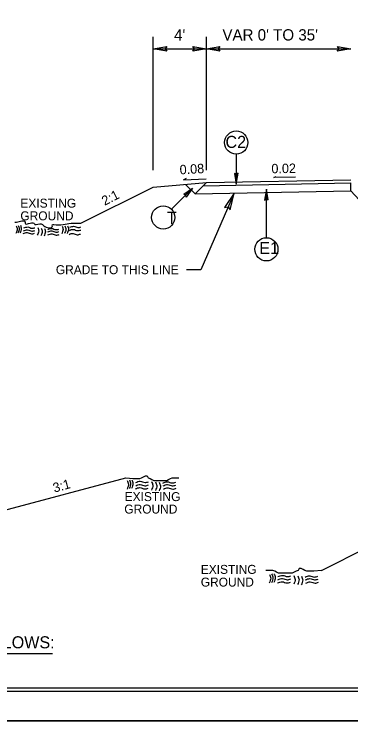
# Model space of a CAD drawing. Extents: x 573813 to 575363, y -54752 to -53123.
# Drawn here: x 574782.7 to 574833.5, y -54223.4 to -54116.8 of the extents above; entities that cross this region are included whole.
import ezdxf

# ---------------------------------------------------------------- set-up
doc = ezdxf.new("R2010")
doc.units = 0
for name, color, linetype in [('Old_Level_1', 7, 'Continuous'), ('Old_Level_11', 7, 'Continuous'), ('Old_Level_2', 7, 'Continuous'), ('Prop Dimension', 7, 'Continuous'), ('Prop Dimension Text', 7, 'Continuous'), ('Sheet Cutting Line CELL', 7, 'Continuous'), ('Sheet Plot Border Inside CELL', 7, 'Continuous'), ('Sheet Plot Border Outside CELL', 7, 'Continuous'), ('Sheet Typical CELL', 7, 'Continuous'), ('Typical ID Circle CELL', 7, 'Continuous'), ('Typical Pavement Slope CELL', 7, 'Continuous'), ('Typical Pavement Slope Information CELL', 7, 'Continuous'), ('Typical Shoulder Slope Information CELL', 7, 'Continuous'), ('Typical Terminator CELL', 7, 'Continuous'), ('Typical Text General CELL', 7, 'Continuous'), ('Typical Text ID Circle CELL', 7, 'Continuous')]:
    doc.layers.add(name, color=color, linetype=linetype)

msp = doc.modelspace()

# ---------------------------------------------------------------- linework, layer by layer
at = {"layer": 'Old_Level_1'}
for p, q in [((574821.89, -54141.45), (574822.27, -54141.27)), ((574825.16, -54141.39), (574821.89, -54141.45)), ((574803.69, -54142.87), (574811.7, -54142.21)), ((574808.26, -54141.8), (574808.71, -54141.51)), ((574808.26, -54141.8), (574811.69, -54141.63)), ((574808.56, -54142.47), (574810, -54143.91)), ((574811.7, -54142.21), (574810, -54143.91)), ((574811.24, -54142.67), (574833.53, -54142.23)), ((574811.7, -54142.21), (574833.53, -54141.77)), ((574792.76, -54148.34), (574803.69, -54142.87)), ((574810, -54143.91), (574833.53, -54143.44)), ((574781.07, -54191.67), (574799.55, -54186.73)), ((574829.1, -54200.71), (574852.24, -54189.13))]:
    msp.add_line(p, q, dxfattribs=at)
for points in [[(574799.55, -54186.73), (574800.67, -54186.87), (574800.95, -54186.87), (574801.37, -54186.87), (574801.65, -54186.87), (574801.93, -54186.73), (574802.21, -54186.59), (574802.49, -54186.45), (574802.77, -54186.45), (574802.91, -54186.73), (574803.19, -54186.87), (574803.47, -54187.01), (574803.75, -54187.15), (574804.03, -54187.15), (574804.31, -54187.15), (574804.59, -54187.15), (574804.87, -54187.15), (574805.15, -54187.15), (574805.43, -54187.15), (574805.71, -54187.15), (574805.99, -54187.01), (574806.27, -54186.87), (574806.55, -54186.73), (574806.97, -54186.73), (574807.25, -54186.73), (574807.53, -54186.73)], [(574829.1, -54200.71), (574827.92, -54200.85), (574827.62, -54200.85), (574827.18, -54200.85), (574826.89, -54200.85), (574826.59, -54200.71), (574826.3, -54200.56), (574826, -54200.41), (574825.71, -54200.41), (574825.56, -54200.71), (574825.26, -54200.85), (574824.97, -54201), (574824.67, -54201.15), (574824.38, -54201.15), (574824.08, -54201.15), (574823.79, -54201.15), (574823.49, -54201.15), (574823.2, -54201.15), (574822.9, -54201.15), (574822.61, -54201.15), (574822.31, -54201), (574822.02, -54200.85), (574821.72, -54200.71), (574821.28, -54200.71), (574820.99, -54200.71), (574820.69, -54200.71)]]:
    msp.add_lwpolyline(points, dxfattribs=at)
at = {"layer": 'Old_Level_11'}
msp.add_line((574736.55, -54213.27), (574788.44, -54213.27), dxfattribs=at)
for points in [[(574805.74, -54122.36), (574803.69, -54122), (574805.75, -54121.64), (574805.49, -54122)], [(574809.66, -54121.65), (574811.7, -54122), (574809.65, -54122.37), (574809.91, -54122)], [(574813.75, -54122.36), (574811.7, -54122), (574813.76, -54121.64), (574813.5, -54122)], [(574831.49, -54121.65), (574833.53, -54122), (574831.48, -54122.37), (574831.74, -54122)]]:
    msp.add_lwpolyline(points, close=True, dxfattribs=at)
at = {"layer": 'Old_Level_2'}
for points in [[(574782.78, -54148.17), (574783.01, -54148.15), (574784.32, -54148.15), (574784.32, -54148.34), (574785.63, -54148.34), (574785.82, -54148.52), (574786.01, -54148.52), (574786.95, -54148.52), (574787.13, -54148.71), (574788.45, -54148.71), (574788.45, -54148.52), (574788.64, -54148.52), (574791.26, -54148.34), (574792.76, -54148.34)], [(574783, -54148.7), (574783.14, -54149.21), (574782.93, -54149.86)], [(574783.29, -54148.66), (574783.44, -54149.16), (574783.23, -54149.81)], [(574783.61, -54148.64), (574783.75, -54149.14), (574783.54, -54149.79)], [(574784.12, -54149.05), (574784.73, -54148.9), (574785.36, -54149.09), (574785.82, -54149.01)], [(574789.91, -54148.76), (574790.06, -54149.27), (574789.85, -54149.92)], [(574790.33, -54148.74), (574790.48, -54149.25), (574790.27, -54149.9)], [(574790.73, -54148.7), (574790.88, -54149.21), (574790.67, -54149.86)], [(574791.06, -54148.94), (574791.66, -54148.8), (574792.3, -54148.98), (574792.76, -54148.9)], [(574784.04, -54149.89), (574784.65, -54149.74), (574785.28, -54149.93), (574785.74, -54149.85)], [(574784.1, -54149.47), (574784.71, -54149.32), (574785.34, -54149.51), (574785.8, -54149.43)], [(574786.23, -54149), (574786.38, -54149.5), (574786.17, -54150.15)], [(574786.76, -54149.06), (574786.91, -54149.56), (574786.7, -54150.21)], [(574787.24, -54149.12), (574787.39, -54149.63), (574787.18, -54150.28)], [(574787.74, -54149.26), (574788.34, -54149.11), (574788.98, -54149.3), (574789.44, -54149.22)], [(574787.74, -54149.64), (574788.34, -54149.49), (574788.98, -54149.68), (574789.44, -54149.59)], [(574787.78, -54150.08), (574788.39, -54149.93), (574789.02, -54150.12), (574789.48, -54150.04)], [(574790.97, -54150.01), (574791.58, -54149.87), (574792.21, -54150.06), (574792.67, -54149.97)], [(574791.03, -54149.41), (574791.64, -54149.26), (574792.27, -54149.45), (574792.74, -54149.36)], [(574799.74, -54187.13), (574799.93, -54187.7), (574799.73, -54188.45)], [(574799.74, -54187.13), (574799.93, -54187.7), (574799.73, -54188.45)], [(574800.07, -54187.07), (574800.26, -54187.63), (574800.06, -54188.38)], [(574800.07, -54187.07), (574800.26, -54187.63), (574800.06, -54188.38)], [(574800.43, -54187.03), (574800.62, -54187.6), (574800.41, -54188.34)], [(574800.43, -54187.03), (574800.62, -54187.6), (574800.41, -54188.34)], [(574801.03, -54187.47), (574801.71, -54187.27), (574802.44, -54187.46), (574802.96, -54187.34)], [(574800.98, -54188.43), (574801.66, -54188.23), (574802.39, -54188.42), (574802.91, -54188.3)], [(574800.98, -54188.43), (574801.66, -54188.23), (574802.39, -54188.42), (574802.91, -54188.3)], [(574801.03, -54187.95), (574801.71, -54187.75), (574802.43, -54187.94), (574802.95, -54187.82)], [(574801.03, -54187.95), (574801.71, -54187.75), (574802.43, -54187.94), (574802.95, -54187.82)], [(574803.42, -54187.31), (574803.61, -54187.87), (574803.41, -54188.62)], [(574803.42, -54187.31), (574803.61, -54187.87), (574803.41, -54188.62)], [(574804.02, -54187.36), (574804.21, -54187.92), (574804.01, -54188.67)], [(574804.02, -54187.36), (574804.21, -54187.92), (574804.01, -54188.67)], [(574804.57, -54187.41), (574804.76, -54187.97), (574804.56, -54188.72)], [(574804.57, -54187.41), (574804.76, -54187.97), (574804.56, -54188.72)], [(574805.14, -54187.54), (574805.82, -54187.34), (574806.54, -54187.53), (574807.07, -54187.41)], [(574805.16, -54187.97), (574805.84, -54187.77), (574806.56, -54187.95), (574807.08, -54187.84)], [(574805.16, -54187.97), (574805.84, -54187.77), (574806.56, -54187.95), (574807.08, -54187.84)], [(574805.23, -54188.46), (574805.91, -54188.27), (574806.63, -54188.45), (574807.15, -54188.33)], [(574805.23, -54188.46), (574805.91, -54188.27), (574806.63, -54188.45), (574807.15, -54188.33)], [(574821.23, -54201.32), (574821.42, -54201.89), (574821.21, -54202.64)], [(574821.23, -54201.32), (574821.42, -54201.89), (574821.21, -54202.64)], [(574821.56, -54201.26), (574821.75, -54201.83), (574821.54, -54202.58)], [(574821.56, -54201.26), (574821.75, -54201.83), (574821.54, -54202.58)], [(574821.91, -54201.22), (574822.11, -54201.79), (574821.9, -54202.54)], [(574821.91, -54201.22), (574822.11, -54201.79), (574821.9, -54202.54)], [(574822.51, -54202.14), (574823.2, -54201.95), (574823.92, -54202.13), (574824.44, -54202.01)], [(574822.51, -54202.14), (574823.2, -54201.95), (574823.92, -54202.13), (574824.44, -54202.01)], [(574822.52, -54201.66), (574823.2, -54201.47), (574823.93, -54201.65), (574824.45, -54201.53)], [(574822.52, -54201.66), (574823.2, -54201.47), (574823.93, -54201.65), (574824.45, -54201.53)], [(574824.91, -54201.5), (574825.1, -54202.07), (574824.9, -54202.82)], [(574824.91, -54201.5), (574825.1, -54202.07), (574824.9, -54202.82)], [(574825.51, -54201.55), (574825.7, -54202.11), (574825.49, -54202.86)], [(574825.51, -54201.55), (574825.7, -54202.11), (574825.49, -54202.86)], [(574826.06, -54201.6), (574826.25, -54202.16), (574826.04, -54202.91)], [(574826.06, -54201.6), (574826.25, -54202.16), (574826.04, -54202.91)], [(574826.62, -54201.73), (574827.31, -54201.53), (574828.03, -54201.72), (574828.55, -54201.6)], [(574826.62, -54201.73), (574827.31, -54201.53), (574828.03, -54201.72), (574828.55, -54201.6)], [(574826.64, -54202.16), (574827.33, -54201.96), (574828.05, -54202.15), (574828.57, -54202.03)], [(574826.64, -54202.16), (574827.33, -54201.96), (574828.05, -54202.15), (574828.57, -54202.03)], [(574822.46, -54202.62), (574823.15, -54202.43), (574823.87, -54202.61), (574824.39, -54202.49)], [(574822.46, -54202.62), (574823.15, -54202.43), (574823.87, -54202.61), (574824.39, -54202.49)], [(574826.71, -54202.65), (574827.4, -54202.46), (574828.12, -54202.64), (574828.64, -54202.52)], [(574826.71, -54202.65), (574827.4, -54202.46), (574828.12, -54202.64), (574828.64, -54202.52)]]:
    msp.add_spline(points, degree=3, dxfattribs=at)
at = {"layer": 'Prop Dimension'}
for p, q in [((574803.69, -54140.32), (574803.69, -54120.18)), ((574811.7, -54140.32), (574811.7, -54120.18)), ((574803.69, -54122), (574811.7, -54122)), ((574811.7, -54122), (574833.53, -54122)), ((574833.53, -54143.44), (574839.62, -54150.05)), ((574815.89, -54143.79), (574810.89, -54155.34)), ((574810.89, -54155.34), (574808.68, -54155.34))]:
    msp.add_line(p, q, dxfattribs=at)
at = {"layer": 'Sheet Cutting Line CELL'}
for p, q in [((575006.71, -54223.42), (574669.73, -54223.42)), ((574669.73, -54223.42), (575006.71, -54223.42))]:
    msp.add_line(p, q, dxfattribs=at)
at = {"layer": 'Sheet Plot Border Inside CELL'}
msp.add_lwpolyline([(575005.81, -54007.8), (574672.33, -54007.8), (574672.33, -54218.93), (575005.81, -54218.93)], close=True, dxfattribs=at)
at = {"layer": 'Sheet Plot Border Outside CELL'}
for p, q in [((574669.73, -54223.42), (575006.71, -54223.42)), ((575006.71, -54223.42), (574669.73, -54223.42))]:
    msp.add_line(p, q, dxfattribs=at)
msp.add_lwpolyline([(575006.71, -54003.31), (574669.73, -54003.31), (574669.73, -54223.42), (575006.71, -54223.42)], close=True, dxfattribs=at)
at = {"layer": 'Sheet Typical CELL'}
msp.add_lwpolyline([(575003.31, -54008.31), (574703.15, -54008.31), (574703.15, -54218.42), (575003.31, -54218.42)], close=True, dxfattribs=at)
at = {"layer": 'Typical ID Circle CELL'}
for p, q in [((574816.21, -54137.9), (574816.21, -54142.43)), ((574806.42, -54146.22), (574809.62, -54143.02)), ((574820.77, -54150.52), (574820.77, -54143.2))]:
    msp.add_line(p, q, dxfattribs=at)
for centre in [(574816.21, -54136.16), (574805.19, -54147.46), (574820.77, -54152.27)]:
    msp.add_circle(centre, 1.75, dxfattribs=at)
at = {"layer": 'Typical Pavement Slope CELL'}
msp.add_line((574833.53, -54143.44), (574833.53, -54142.23), dxfattribs=at)
at = {"layer": 'Typical Terminator CELL'}
for points in [[(574815.93, -54140.81), (574816.21, -54142.43), (574816.5, -54140.8), (574816.21, -54141)], [(574808.28, -54143.97), (574809.62, -54143.02), (574808.67, -54144.38), (574808.62, -54144.03)], [(574821.05, -54144.82), (574820.77, -54143.2), (574820.48, -54144.83), (574820.77, -54144.62)], [(574815.28, -54146.31), (574815.89, -54143.79), (574814.45, -54145.97), (574815, -54145.85)]]:
    msp.add_lwpolyline(points, close=True, dxfattribs=at)

# ---------------------------------------------------------------- texts
at = {"layer": 'Old_Level_1'}
for s, height, rotation, p in [('2:1', 1.421, 27.0855, (574796.34, -54145.71)), ('EXISTING', 1.35, 360, (574783.61, -54145.98)), ('GROUND', 1.35, 360, (574783.61, -54147.89)), ('3:1', 1.421, 15.635, (574788.75, -54188.99)), ('EXISTING', 1.35, 360, (574799.36, -54190.26)), ('GROUND', 1.35, 360, (574799.31, -54192.14)), ('EXISTING', 1.35, 360, (574810.86, -54201.24)), ('GROUND', 1.35, 360, (574810.86, -54203.16)), ('USE TYPICAL SECTION NO. 14 AS FOLLOWS:', 1.8192, 360, (574735.93, -54212.48))]:
    msp.add_text(s, height=height, rotation=rotation, dxfattribs=at).set_placement(p)
at = {"layer": 'Prop Dimension Text'}
for s, height, p in [("VAR 0' TO 35'", 1.7055, (574814.13, -54120.76)), ("4'", 1.705, (574806.82, -54120.78))]:
    msp.add_text(s, height=height, dxfattribs=at).set_placement(p)
at = {"layer": 'Typical Pavement Slope Information CELL'}
msp.add_text('0.02', height=1.421, rotation=0.9101, dxfattribs=at).set_placement((574821.54, -54140.8))
at = {"layer": 'Typical Shoulder Slope Information CELL'}
msp.add_text('0.08', height=1.421, rotation=3.2469, dxfattribs=at).set_placement((574807.71, -54140.97))
at = {"layer": 'Typical Text General CELL'}
msp.add_text('GRADE TO THIS LINE', height=1.3498, dxfattribs=at).set_placement((574788.97, -54156.02))
at = {"layer": 'Typical Text ID Circle CELL'}
for s, p in [('C2', (574814.59, -54136.97)), ('E1', (574819.7, -54152.99))]:
    msp.add_text(s, height=1.819, dxfattribs=at).set_placement(p)
msp.add_text('T', height=1.82, rotation=360, dxfattribs=at).set_placement((574805.73, -54148.43))

doc.saveas('drawing.dxf')
